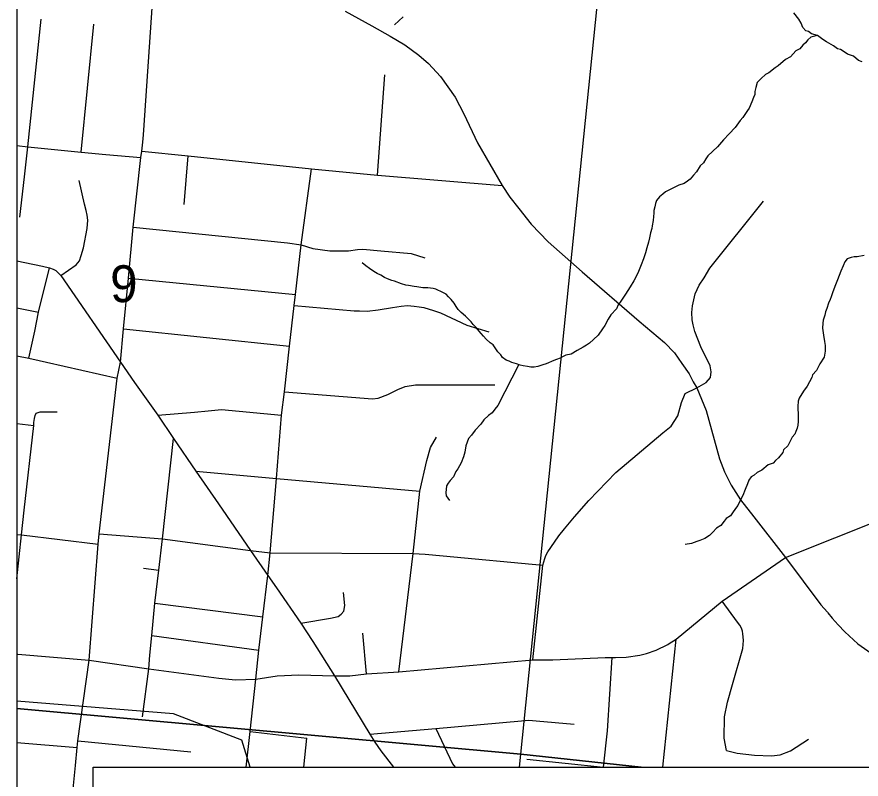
# Model space of a CAD drawing. Extents: x -8.2 to 38.5, y -0.1 to 21.9.
# Drawn here: x 2.163 to 3.122, y 17.376 to 18.241 of the extents above; entities that cross this region are included whole.
import ezdxf

# ---------------------------------------------------------------- set-up
doc = ezdxf.new("R2010")
doc.units = 0
for name, color, linetype in [('Default', 7, 'Continuous'), ('GM_X_Adjacent_County', 7, 'Continuous'), ('GM_X_Adjacent_County_Text', 7, 'Continuous'), ('GM_X_County_Road_Text', 7, 'Continuous'), ('GM_X_Minor_River', 7, 'Continuous'), ('GM_X_Section', 7, 'Continuous'), ('GM_X_Township_Subdivision_Text', 7, 'Continuous'), ('GM_X_Township_Text', 7, 'Continuous'), ('GM_X_US_Location', 7, 'Continuous')]:
    doc.layers.add(name, color=color, linetype=linetype)

msp = doc.modelspace()

# ---------------------------------------------------------------- linework, layer by layer
at = {"layer": 'Default'}
for points in [[(3.74862, 17.38985), (3.81842, 18.05156), (3.84352, 18.28947), (3.84494, 18.30297), (3.84719, 18.32786), (3.88536, 18.75168), (3.92891, 19.23533), (3.94356, 19.39793), (3.99614, 19.98173), (4.03018, 20.35971), (4.0404, 20.46486), (4.04668, 20.55326), (4.06654, 20.76352), (4.06663, 20.76446), (2.16338, 20.76446), (2.16338, 15.43171)], [(2.16338, 18.31409), (2.16338, 14.83147)], [(2.73384, 17.38985), (2.73536, 17.40463), (2.16338, 17.45649), (2.16338, 16.44648), (2.63305, 16.4084), (2.65991, 16.66998)]]:
    msp.add_lwpolyline(points, dxfattribs=at)
msp.add_lwpolyline([(2.16338, 18.47186), (2.16338, 17.45649), (2.73536, 17.40463), (2.83734, 18.40237)], close=True, dxfattribs=at)
at = {"layer": 'GM_X_Adjacent_County'}
msp.add_lwpolyline([(2.24986, 17.38985), (5.03564, 17.38985), (5.03564, 16.66998), (2.24986, 16.66998)], close=True, dxfattribs=at)
at = {"layer": 'GM_X_Adjacent_County_Text'}
for points in [[(2.87221, 17.38985), (2.73536, 17.40463), (2.83734, 18.40237), (3.84833, 18.30047), (3.75128, 17.38985)], [(2.73384, 17.38985), (2.73536, 17.40463), (2.87221, 17.38985)]]:
    msp.add_lwpolyline(points, dxfattribs=at)
at = {"layer": 'GM_X_Minor_River'}
for points in [[(2.60198, 18.24157), (2.59223, 18.23232)], [(3.12311, 18.19044), (3.11897, 18.19208), (3.11301, 18.19682), (3.10623, 18.19929), (3.10249, 18.20168), (3.09839, 18.20446), (3.09499, 18.20532), (3.09051, 18.20849), (3.08265, 18.21328), (3.07816, 18.21569), (3.0722, 18.22043), (3.0654, 18.22214), (3.06205, 18.2249), (3.05903, 18.22575), (3.05571, 18.22927), (3.05356, 18.23428), (3.05102, 18.23892), (3.04551, 18.24593)], [(3.0722, 18.22043), (3.06454, 18.21836), (3.06142, 18.2154), (3.05866, 18.21205), (3.05555, 18.20947), (3.0524, 18.20537), (3.04777, 18.20283), (3.0415, 18.19615), (3.0361, 18.19326), (3.02753, 18.18588), (3.02405, 18.18369), (3.01705, 18.17779), (3.0132, 18.176), (3.00813, 18.17157), (3.00383, 18.16712), (3.00215, 18.16145), (3.00127, 18.15691), (3.00118, 18.15348), (2.99956, 18.1501), (2.99791, 18.14519), (2.99467, 18.13805), (2.99269, 18.13506), (2.98753, 18.1272), (2.9844, 18.12386), (2.97887, 18.11602), (2.97182, 18.1086), (2.96555, 18.10192), (2.95888, 18.09411), (2.94795, 18.08375), (2.94558, 18.08039), (2.94279, 18.0759), (2.9389, 18.07258), (2.93491, 18.06545), (2.93138, 18.06174), (2.92784, 18.05727), (2.92474, 18.05507), (2.92086, 18.05252), (2.91472, 18.0504), (2.91125, 18.0486), (2.90432, 18.04536), (2.89969, 18.04283), (2.89657, 18.04025), (2.89307, 18.0373), (2.88954, 18.03321), (2.8883, 18.02981), (2.88744, 18.02603), (2.88657, 18.02187), (2.88648, 18.01882), (2.886, 18.01503), (2.88588, 18.01046), (2.88457, 18.0044), (2.88411, 18.00137), (2.88284, 17.99645), (2.88154, 17.99078), (2.88027, 17.98586), (2.87857, 17.97944), (2.8769, 17.97377), (2.87481, 17.96697), (2.87197, 17.96019), (2.8691, 17.95266), (2.86669, 17.94777), (2.86386, 17.94176), (2.8595, 17.93503), (2.85433, 17.92679), (2.84838, 17.91782), (2.84602, 17.91484), (2.844, 17.91032), (2.83772, 17.90326), (2.83455, 17.8984), (2.83093, 17.89126), (2.82817, 17.88753), (2.82341, 17.88043), (2.81795, 17.87525), (2.81327, 17.87119), (2.81017, 17.86899), (2.80631, 17.86682), (2.79936, 17.86282), (2.79278, 17.85882), (2.78666, 17.85746), (2.78358, 17.85603), (2.78011, 17.85422), (2.77589, 17.85281), (2.7728, 17.85137), (2.76434, 17.8478), (2.76051, 17.84677), (2.75475, 17.84465), (2.75055, 17.844), (2.74675, 17.84411), (2.74296, 17.84459), (2.73804, 17.84549), (2.73464, 17.84635), (2.73049, 17.84761), (2.72521, 17.84928), (2.72222, 17.85089), (2.71882, 17.85174), (2.71472, 17.8549), (2.7129, 17.858), (2.70919, 17.86153)], [(3.12514, 17.97064), (3.11712, 17.96934), (3.11407, 17.96904), (3.11063, 17.96838), (3.10602, 17.96698), (3.10327, 17.96363), (3.10125, 17.95912), (3.09879, 17.95271), (3.0951, 17.94291), (3.09186, 17.93539), (3.08938, 17.92822), (3.08774, 17.9237), (3.08652, 17.92069), (3.08488, 17.91654), (3.08282, 17.91051), (3.0812, 17.90674), (3.08071, 17.90295), (3.07866, 17.89729), (3.07818, 17.89388), (3.07803, 17.88817), (3.07895, 17.88015), (3.08029, 17.87325), (3.08092, 17.86866), (3.08113, 17.86219), (3.0798, 17.85537), (3.07504, 17.84788), (3.07102, 17.84), (3.06671, 17.83517), (3.06586, 17.83214), (3.06066, 17.82239), (3.05632, 17.81679), (3.05154, 17.80893), (3.05031, 17.80554), (3.04977, 17.79946), (3.05005, 17.79602), (3.05032, 17.79183), (3.05021, 17.78764), (3.05044, 17.7823), (3.04995, 17.77812), (3.04909, 17.77472)], [(2.70919, 17.86153), (2.70408, 17.86929), (2.70072, 17.87167), (2.69627, 17.87561), (2.69294, 17.87912), (2.69036, 17.88225), (2.68447, 17.88926), (2.68151, 17.89239), (2.67893, 17.89551), (2.67559, 17.89865), (2.67264, 17.90178), (2.66781, 17.90611), (2.66447, 17.90925), (2.66191, 17.91275), (2.65973, 17.91662), (2.65642, 17.9209), (2.65345, 17.92365), (2.65088, 17.92676), (2.64675, 17.92879), (2.63886, 17.93243), (2.63584, 17.93328), (2.62977, 17.93383), (2.62407, 17.93399), (2.61725, 17.93494), (2.61422, 17.93541), (2.60779, 17.93673), (2.60477, 17.93719), (2.59986, 17.93848), (2.59195, 17.94136), (2.58893, 17.94221), (2.58404, 17.94425), (2.58066, 17.94587), (2.57654, 17.94827), (2.57241, 17.95029), (2.56868, 17.95268), (2.56382, 17.95586), (2.55934, 17.95903), (2.55525, 17.96219)], [(2.73315, 17.8468), (2.70944, 17.80059), (2.7059, 17.79612), (2.70275, 17.79202), (2.69886, 17.78908), (2.69341, 17.78428), (2.69023, 17.77942), (2.68358, 17.77237), (2.67963, 17.76676), (2.6761, 17.76305), (2.67447, 17.75891), (2.67321, 17.75476), (2.67188, 17.74756), (2.67021, 17.74227), (2.66775, 17.73548), (2.66414, 17.72873), (2.66177, 17.72537), (2.65894, 17.71935), (2.65541, 17.71526), (2.65305, 17.71228), (2.65107, 17.70929), (2.65047, 17.70131), (2.65076, 17.69787), (2.65442, 17.69282)], [(3.04909, 17.77472), (3.04785, 17.77095), (3.04663, 17.76793), (3.0435, 17.76459), (3.03867, 17.75483), (3.03359, 17.75002), (3.03275, 17.74699), (3.02803, 17.74103), (3.02452, 17.73808), (3.02178, 17.73511), (3.0164, 17.73298), (3.00902, 17.72709), (3.00363, 17.72458), (3.00049, 17.72123), (2.99702, 17.71943), (2.99426, 17.7157), (2.99262, 17.71155), (2.99017, 17.70515), (2.98732, 17.69837), (2.98411, 17.69199), (2.98169, 17.6871), (2.97932, 17.68374), (2.97576, 17.67851), (2.97338, 17.67515), (2.96874, 17.67223), (2.96638, 17.66925), (2.96244, 17.66441), (2.95779, 17.66111), (2.95349, 17.65666), (2.94958, 17.65296), (2.94455, 17.64967), (2.93878, 17.64717), (2.93533, 17.64612), (2.92919, 17.64401), (2.92192, 17.64269)]]:
    msp.add_lwpolyline(points, dxfattribs=at)
at = {"layer": 'GM_X_Section'}
msp.add_lwpolyline([(8.96338, 15.31357), (8.96338, 20.76446), (2.16338, 20.76446), (2.16338, 13.96446)], dxfattribs=at)
at = {"layer": 'GM_X_Township_Subdivision_Text'}
for p, q in [((2.23649, 18.0878), (2.25071, 18.23337)), ((2.57263, 18.06198), (2.58093, 18.17573)), ((2.26453, 18.08532), (2.30428, 18.08176)), ((2.35333, 18.02854), (2.3577, 18.08363)), ((2.29015, 17.94496), (2.47969, 17.92642)), ((2.16338, 17.91135), (2.18789, 17.90641)), ((2.28456, 17.88742), (2.47293, 17.86762)), ((2.16338, 17.78007), (2.18246, 17.77758)), ((2.30713, 17.61566), (2.32445, 17.61346)), ((2.32003, 17.57594), (2.44272, 17.56058)), ((2.31654, 17.53946), (2.43812, 17.52277)), ((2.56045, 17.49589), (2.55595, 17.54199)), ((2.30591, 17.44697), (2.3132, 17.50166)), ((2.42811, 17.43065), (2.49262, 17.42305)), ((2.16338, 17.41804), (2.23196, 17.41222)), ((2.23275, 17.41997), (2.3608, 17.40733)), ((2.48912, 17.38985), (2.49262, 17.42305)), ((2.74237, 17.39901), (2.82949, 17.39004))]:
    msp.add_line(p, q, dxfattribs=at)
for points in [[(2.16689, 18.01413), (2.17206, 18.06006), (2.17584, 18.09407), (2.19086, 18.23894)], [(2.16338, 18.09543), (2.17584, 18.09407), (2.23649, 18.0878), (2.26453, 18.08532)], [(2.44819, 17.60764), (2.45078, 17.63308), (2.45826, 17.71744), (2.46396, 17.78955), (2.467, 17.81603), (2.47293, 17.86762), (2.47827, 17.91409), (2.47969, 17.92642), (2.48618, 17.98282), (2.49786, 18.06901)], [(2.21337, 17.94787), (2.23064, 17.95992), (2.23445, 17.96481), (2.23644, 17.97067), (2.23898, 17.97927), (2.24326, 18.00135), (2.24375, 18.0106), (2.24306, 18.01656), (2.24186, 18.02163), (2.24017, 18.02889), (2.2342, 18.05589)], [(2.93545, 17.82041), (2.94584, 17.8266), (2.95079, 17.83217), (2.95172, 17.83852), (2.95048, 17.84548), (2.93981, 17.86699), (2.93284, 17.88432), (2.93098, 17.8919), (2.9299, 17.89778), (2.92975, 17.90582), (2.93052, 17.9134), (2.93331, 17.92717), (2.9381, 17.93692), (2.94352, 17.94543), (2.95002, 17.95626), (3.01095, 18.0322)], [(2.29525, 18.00299), (2.47041, 17.98487), (2.48618, 17.98282), (2.49927, 17.97862), (2.5188, 17.97609), (2.53984, 17.97584), (2.55011, 17.97761), (2.55622, 17.97799), (2.57657, 17.97591), (2.61104, 17.973), (2.62649, 17.96806)], [(2.17698, 17.85425), (2.18372, 17.88493), (2.18789, 17.90641), (2.20043, 17.95676)], [(2.47827, 17.91409), (2.54621, 17.90788), (2.55249, 17.90781), (2.56088, 17.9076), (2.57337, 17.90887), (2.58971, 17.91158), (2.59485, 17.91227), (2.59954, 17.91325), (2.60688, 17.91381), (2.61441, 17.91303), (2.61996, 17.9124), (2.62541, 17.91161), (2.63624, 17.90836), (2.64424, 17.90547), (2.67423, 17.89174), (2.69931, 17.88417)], [(2.16338, 17.85698), (2.17698, 17.85425), (2.27717, 17.83136)], [(2.467, 17.81603), (2.567, 17.80812), (2.57355, 17.80863), (2.58451, 17.81291), (2.59584, 17.81872), (2.60417, 17.82211), (2.61602, 17.82375), (2.70611, 17.82401)], [(2.76621, 17.63443), (2.77378, 17.64533), (2.77857, 17.65251), (2.78512, 17.66057), (2.79659, 17.67405), (2.81277, 17.69258), (2.84344, 17.7244), (2.89659, 17.76944), (2.90605, 17.77712), (2.91378, 17.78877), (2.91804, 17.8038), (2.92187, 17.81403), (2.93545, 17.82041)], [(2.18246, 17.77758), (2.18275, 17.7813), (2.1834, 17.78575), (2.18421, 17.78926), (2.18535, 17.79176), (2.18976, 17.79335), (2.19669, 17.79342), (2.20911, 17.79342)], [(2.32333, 17.78937), (2.36501, 17.79307), (2.38064, 17.79458), (2.39575, 17.79584), (2.46396, 17.78955)], [(2.16338, 17.60383), (2.16856, 17.6535), (2.1715, 17.68184), (2.18246, 17.77758)], [(2.3132, 17.50166), (2.31442, 17.51716), (2.31654, 17.53946), (2.32003, 17.57594), (2.32445, 17.61346), (2.3287, 17.64901), (2.34131, 17.76286)], [(2.59688, 17.49816), (2.61312, 17.63234), (2.62093, 17.70304), (2.62862, 17.7382), (2.6329, 17.75281), (2.63983, 17.76453)], [(2.36667, 17.72596), (2.45826, 17.71744), (2.62093, 17.70304)], [(2.16338, 17.65391), (2.16856, 17.6535), (2.25557, 17.64326)], [(2.25677, 17.65494), (2.3287, 17.64901), (2.42858, 17.63604), (2.45078, 17.63308), (2.61312, 17.63234), (2.62673, 17.63159), (2.64714, 17.62983), (2.76061, 17.61943)], [(2.74902, 17.51188), (2.76061, 17.61943), (2.76275, 17.62686), (2.76395, 17.63033), (2.76621, 17.63443)], [(2.48581, 17.55343), (2.51949, 17.55894), (2.52804, 17.56091), (2.53166, 17.56371), (2.53462, 17.56716), (2.53577, 17.57357), (2.53413, 17.58836)], [(2.96878, 17.40911), (2.96638, 17.42296), (2.96669, 17.44725), (2.97009, 17.46366), (2.97559, 17.48369), (2.98742, 17.52462), (2.98843, 17.53382), (2.98804, 17.53777), (2.98762, 17.54125), (2.98707, 17.54423), (2.98584, 17.54771), (2.98391, 17.55103), (2.98135, 17.55467), (2.96399, 17.5784)], [(2.89686, 17.38985), (2.89687, 17.39004), (2.9118, 17.53541)], [(2.82946, 17.38985), (2.82949, 17.39004), (2.83398, 17.4312), (2.83901, 17.51456)], [(2.56421, 17.42758), (2.63903, 17.43402), (2.7362, 17.44272), (2.74458, 17.44323), (2.75291, 17.4426), (2.7961, 17.43866)], [(2.63903, 17.43402), (2.65789, 17.39386), (2.6611, 17.38985)], [(2.96878, 17.40911), (2.98116, 17.40579), (3.00088, 17.40346), (3.02007, 17.40269), (3.03005, 17.40416), (3.0415, 17.4085), (3.06192, 17.42164)]]:
    msp.add_lwpolyline(points, dxfattribs=at)
at = {"layer": 'GM_X_Township_Text'}
msp.add_line((2.16338, 17.51825), (2.16462, 17.51815), dxfattribs=at)
for points in [[(2.30628, 18.09948), (2.30699, 18.10779), (2.31787, 18.26315), (2.31875, 18.27129), (2.3199, 18.28184)], [(2.53588, 18.24804), (2.5664, 18.23134), (2.58728, 18.21977), (2.60367, 18.20968), (2.61952, 18.19787), (2.63085, 18.18856), (2.64421, 18.1738), (2.66098, 18.15051), (2.67077, 18.1314), (2.68629, 18.09863), (2.71434, 18.05015), (2.72297, 18.03673), (2.73303, 18.02411), (2.74725, 18.00622), (2.76658, 17.98625), (2.80524, 17.95206), (2.86979, 17.89614), (2.89839, 17.87186), (2.90989, 17.86019), (2.91836, 17.84805), (2.92666, 17.83639), (2.9313, 17.82713), (2.93545, 17.82041), (2.94584, 17.79469), (2.96116, 17.73976), (2.96688, 17.72514), (2.97427, 17.71021), (2.98487, 17.69327), (3.00003, 17.67408), (3.03593, 17.62797), (3.076, 17.57428), (3.08359, 17.56608), (3.08417, 17.56533)], [(2.28082, 17.84954), (2.28456, 17.88742), (2.29015, 17.94496), (2.29525, 18.00299), (2.30428, 18.08176), (2.3054, 18.0891), (2.30628, 18.09948)], [(2.3054, 18.0891), (2.3577, 18.08363), (2.49786, 18.06901), (2.57263, 18.06198), (2.71434, 18.05015)], [(2.16338, 17.96471), (2.17252, 17.96279), (2.19259, 17.95843), (2.20043, 17.95676)], [(2.20043, 17.95676), (2.20466, 17.95535), (2.2077, 17.95371), (2.21024, 17.95113), (2.21337, 17.94787)], [(2.21337, 17.94787), (2.28082, 17.84954), (2.29708, 17.82638), (2.32333, 17.78937), (2.34131, 17.76286), (2.36667, 17.72596), (2.39239, 17.68872), (2.42858, 17.63604), (2.44819, 17.60764), (2.45805, 17.59368), (2.48581, 17.55343), (2.49922, 17.53264), (2.52404, 17.49361), (2.56421, 17.42758), (2.56984, 17.41824), (2.57671, 17.40851), (2.59074, 17.38985)], [(2.19373, 17.01506), (2.2055, 17.11423), (2.2148, 17.23488), (2.2258, 17.34945), (2.22662, 17.35794), (2.22989, 17.39196), (2.23196, 17.41222), (2.23275, 17.41997), (2.2453, 17.51153), (2.25557, 17.64326), (2.25677, 17.65494), (2.27717, 17.83136), (2.28082, 17.84954)], [(2.904, 17.53032), (2.9118, 17.53541), (2.96399, 17.5784), (3.03593, 17.62797), (3.14798, 17.67242)], [(2.42379, 17.38985), (2.42811, 17.43065), (2.43461, 17.48986), (2.43812, 17.52277), (2.44272, 17.56058), (2.44819, 17.60764)], [(3.08417, 17.56533), (3.08885, 17.55927), (3.09581, 17.55169), (3.10326, 17.54363), (3.11812, 17.52981), (3.13312, 17.51941), (3.14813, 17.50975), (3.16863, 17.50039), (3.18527, 17.49505), (3.20815, 17.48985), (3.25917, 17.48454), (3.29116, 17.48054), (3.30932, 17.47678), (3.34697, 17.46823), (3.36769, 17.4624), (3.37597, 17.45954), (3.38913, 17.45465), (3.50642, 17.40419), (3.51834, 17.39869)], [(2.52404, 17.49361), (2.54137, 17.49368), (2.56045, 17.49589), (2.59688, 17.49816), (2.74902, 17.51188), (2.7717, 17.51181), (2.83134, 17.5145), (2.83901, 17.51456), (2.8431, 17.51459), (2.85501, 17.51476), (2.87049, 17.51695), (2.87813, 17.51904), (2.88913, 17.52288), (2.90244, 17.5293), (2.904, 17.53032)], [(2.16462, 17.51815), (2.2453, 17.51153), (2.3132, 17.50166), (2.39257, 17.49118), (2.41156, 17.48921), (2.43461, 17.48986), (2.45884, 17.4935), (2.48349, 17.49482), (2.52404, 17.49361)]]:
    msp.add_lwpolyline(points, dxfattribs=at)
at = {"layer": 'GM_X_US_Location'}
msp.add_lwpolyline([(2.42823, 17.38985), (2.41877, 17.42061), (2.3412, 17.45048), (2.16338, 17.46489)], dxfattribs=at)

# ---------------------------------------------------------------- texts
at = {"layer": 'GM_X_County_Road_Text'}
msp.add_text('9', height=0.04186, rotation=0.00001, dxfattribs=at).set_placement((2.26922, 17.91773))

doc.saveas('drawing.dxf')
